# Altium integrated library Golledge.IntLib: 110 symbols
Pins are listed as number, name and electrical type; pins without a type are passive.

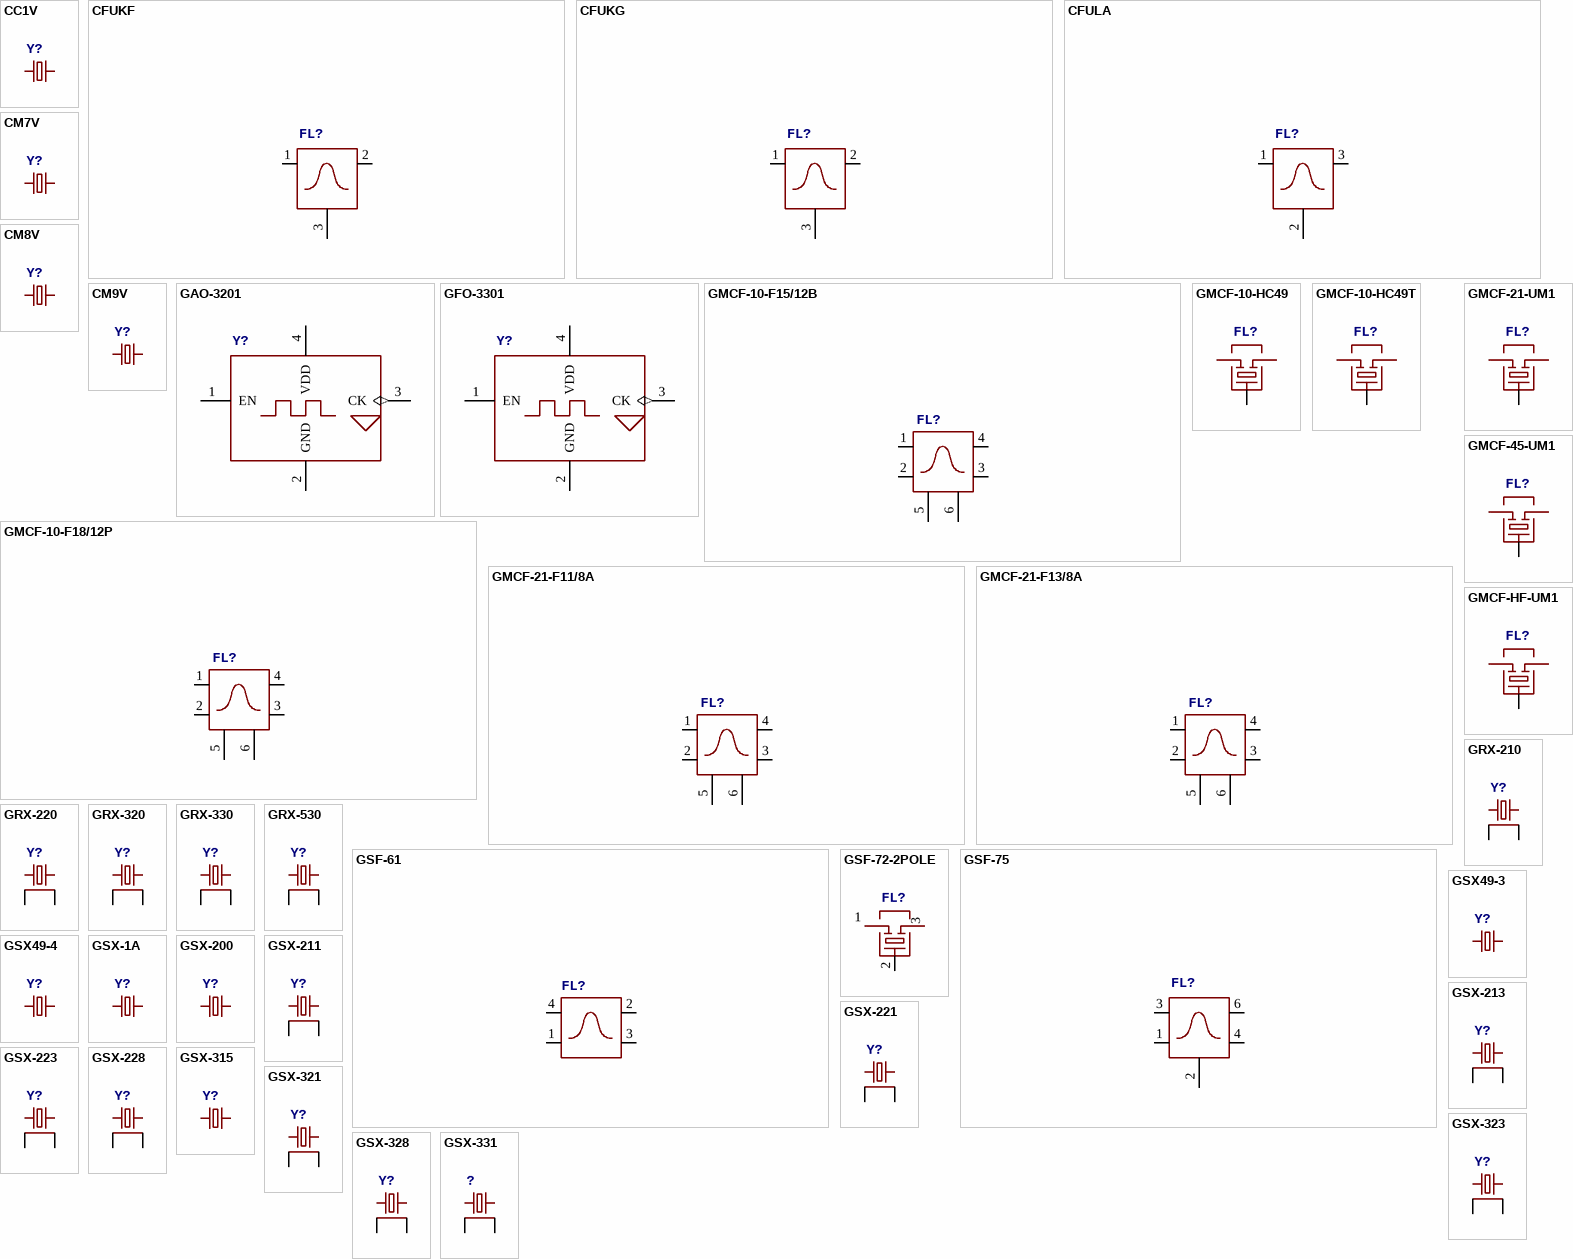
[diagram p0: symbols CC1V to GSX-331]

## CC1V
designator Y?  (value not drawn)
Crystal ¦SM¦ 8.0 x 3.7 mm ¦ Frequency Range 10kHz - 2.1 MHz; Latest Revision Note: Created
footprint CC1V
pins: '1' 1, '2' 2

## CFUKF
designator FL?  (value not drawn)
Ceramic Filter ¦SM¦ Murata¦ Frequency Range 455 kHz; Latest Revision Note: Created
footprint D0278-A
pins: 1 IN, 2 OUT, 3 GND

## CFUKG
designator FL?  (value not drawn)
Ceramic Filter ¦SM¦ Murata¦ Frequency Range 455 kHz; Latest Revision Note: Created
footprint D0278-A
pins: 1 IN, 2 OUT, 3 GND

## CFULA
designator FL?  (value not drawn)
Ceramic Filter ¦Leaded¦ Murata¦ Frequency Range 455 kHz; Latest Revision Note: Created
footprint D0274-A
pins: 1 IN, 2 GND, 3 OUT

## CM7V
designator Y?  (value not drawn)
Crystal ¦SM¦ 3.2 x 1.5 mm ¦ Tuning Fork (Watch)¦ Frequency Range 32.768kHz; Latest Revision Note: Created
footprint CM7V
pins: 1, 2

## CM8V
designator Y?  (value not drawn)
Crystal ¦SM¦ 2 x 1.2 mm ¦ Tuning Fork (Watch)¦ Frequency Range 32.768kHz; Latest Revision Note: Created
footprint CM8V
pins: 1, 2

## CM9V
designator Y?  (value not drawn)
Crystal ¦SM¦ 1.6 x 1.0 mm ¦ Tuning Fork (Watch)¦ Frequency Range 32.768kHz; Latest Revision Note: Created
footprint D0351-A
pins: 1, 2

## GAO-3201
designator Y?  (value not drawn)
Oscillator ¦SM¦ 2.5 x 2.0 mm ¦ CMOS output ¦ Frequency Range 32.768kHz; Latest Revision Note: Created
footprint OSC2520
pins: 1 EN, 2 GND (power), 3 CK (out), 4 VDD (power)

## GFO-3301
designator Y?  (value not drawn)
Oscillator ¦SM¦ 3.2 x 2.5 mm ¦ CMOS output ¦ Frequency Range 32.768kHz; Latest Revision Note: Created
footprint OSC3225
pins: 1 EN, 2 GND (power), 3 CK (out), 4 VDD (power)

## GMCF-10-F15/12B
designator FL?  (value not drawn)
Crystal Filters ¦Leaded¦ 6 pole ¦ Frequency Range 10.7 MHz; Latest Revision Note: Created
footprint F15/12B
pins: 1 IN, 2 GND@1, 3 GND@2, 4 OUT, 5 CASE@1, 6 CASE@2

## GMCF-10-F18/12P
designator FL?  (value not drawn)
Crystal Filters ¦Leaded¦ 8 pole ¦ Frequency Range 10.7 MHz; Latest Revision Note: Created
footprint F18/12P
pins: 1 IN, 2 GND@1, 3 GND@2, 4 OUT, 5 CASE@1, 6 CASE@2

## GMCF-10-HC49
designator FL?  (value not drawn)
Crystal Filter ¦Leaded¦ Monolithic¦ Frequency Range 10.7 MHz; Latest Revision Note: Created
footprint HC49U
pins: 1, 2, 3

## GMCF-10-HC49T
designator FL?  (value not drawn)
Crystal Filter ¦Leaded¦ Monolithic¦ Frequency Range 10.7 MHz; Latest Revision Note: Created
footprint HC49U
pins: 1, 2, 3

## GMCF-21-F11/8A
designator FL?  (value not drawn)
Crystal Filters ¦Leaded¦ 6 and 8 pole ¦ Frequency Range 21.4 MHz; Latest Revision Note: Created
footprint F11/8A
pins: 1 IN, 2 GND@1, 3 GND@2, 4 OUT, 5 CASE@1, 6 CASE@2

## GMCF-21-F13/8A
designator FL?, comment GMCF-21-EF13/8A  (value not drawn)
Crystal Filters ¦Leaded¦ 10 pole ¦ Frequency Range 10.7 - 21.4 MHz; Latest Revision Note: Created
footprint F13/8A
pins: 1 IN, 2 GND@1, 3 GND@2, 4 OUT, 5 CASE_1, 6 CASE_2

## GMCF-21-UM1
designator FL?  (value not drawn)
Crystal Filter ¦Leaded¦ Monolithic¦ Frequency Range 21.4 MHz; Latest Revision Note: Created
footprint UM1
footprint UM4
footprint UM5
pins: 1, 2, 3

## GMCF-45-UM1
designator FL?  (value not drawn)
Crystal Filter ¦Leaded¦ Monolithic¦ Frequency Range 45 MHz; Latest Revision Note: Created
footprint UM1
footprint UM4
footprint UM5
pins: 1, 2, 3

## GMCF-HF-UM1
designator FL?  (value not drawn)
Crystal Filter ¦Leaded¦ Monolithic¦ Frequency Range 55 - 90 MHz; Latest Revision Note: Created
footprint UM1
footprint UM4
footprint UM5
pins: 1, 2, 3

## GRX-210
designator Y?  (value not drawn)
Crystal ¦SM¦ 1.6 x 1.2 mm ¦ AT cut ¦ Frequency Range 26 - 40 MHz; Latest Revision Note: Created
footprint GSX-211
pins: 1, 2, 3, 4

## GRX-220
designator Y?
Crystal ¦SM¦ 2.0 x 1.6 mm ¦ AT cut ¦ Frequency Range 16 - 26 MHz; Latest Revision Note: Created
footprint GSX-221
pins: 1, 2, 3, 4

## GRX-320
designator Y?  (value not drawn)
Crystal ¦SM¦ 2.5 x 2.0 mm ¦ AT cut ¦ Frequency Range 12 - 40 MHz; Latest Revision Note: Created
footprint OSC2520
pins: 1, 2, 3, 4

## GRX-330
designator Y?  (value not drawn)
Crystal ¦SM¦ 3.2 x 2.5 mm ¦ AT cut ¦ Frequency Range 12 - 40 MHz; Latest Revision Note: Created
footprint OSC3225
pins: 1, 2, 3, 4

## GRX-530
designator Y?  (value not drawn)
Crystal ¦SM¦ 5.0 x 3.2 mm ¦ AT cut ¦ Frequency Range 9.8 - 40 MHz; Latest Revision Note: Created
footprint GSX-531
pins: 1, 2, 3, 4

## GSF-61
designator FL?  (value not drawn)
Crystal Filter ¦SM¦ 6.0 x 3.5 ¦ Frequency Range 20 - 45 MHz; Latest Revision Note: Created
footprint D0216-A
pins: 1 INBAR_OR_GND@1, 2 OUT, 3 OUTBAR_OR_GND@2, 4 IN

## GSF-72-2POLE
designator FL?  (value not drawn)
Crystal Filter ¦SM¦ Monolithic¦ Frequency Range 21.4 - 45 MHz; Latest Revision Note: Created
footprint GSF-72
pins: 1, 2, 3

## GSF-75
designator FL?  (value not drawn)
Crystal Filter ¦SM¦ 7.0 x 5.0 ¦ Frequency Range 21.4 - 75 MHz; Latest Revision Note: Created
footprint GSF-75
pins: 1 INBAR_OR_GND@1, 2 COUPLING_CAP, 3 IN, 4 OUTBAR_OR_GND@2, 6 OUT

## GSX49-3
designator Y?  (value not drawn)
Crystal ¦SM¦ 12.3 x 4.7 mm ¦ Low cost ¦ Frequency Range 3.18 - 90 MHz; Latest Revision Note: Created
footprint GSX49-3
pins: 1, 2

## GSX49-4
designator Y?  (value not drawn)
Crystal ¦SM¦ 12.3 x 4.7 mm ¦ Low cost ¦ Frequency Range 3.18 - 90 MHz; Latest Revision Note: Created
footprint GSX49-4
pins: 1, 2

## GSX-1A
designator Y?  (value not drawn)
Crystal ¦SM¦ 7.5 x 5.0 mm ¦ Low cost ¦ Frequency Range 5.0 - 84 MHz; Latest Revision Note: Created
footprint D0118-C
pins: 1, 2

## GSX-200
designator Y?  (value not drawn)
Crystal ¦SM¦ 7.9 x 3.7 mm ¦ Plastic moulded Tuning Fork (Watch) ¦ Frequency Range 32.768kHz; Latest Revision Note: Created
footprint GSX-200
pins: 1, 4 2

## GSX-211
designator Y?  (value not drawn)
Crystal ¦SM¦ 1.6 x 1.2 mm ¦ AT cut ¦ Frequency Range 24 - 54 MHz; Latest Revision Note: Created
footprint GSX-211
pins: 1, 2, 3, 4

## GSX-213
designator Y?  (value not drawn)
Crystal ¦SM¦ 1.6 x 1.2 mm ¦ AT cut ¦ Frequency Range 26 - 60 MHz; Latest Revision Note: Created
footprint GSX-211
pins: 1, 2, 3, 4

## GSX-221
designator Y?  (value not drawn)
Crystal ¦SM¦ 2.0 x 1.6 mm ¦ AT cut ¦ Frequency Range 16 - 56 MHz; Latest Revision Note: Created
footprint GSX-221
pins: 1, 2, 3, 4

## GSX-223
designator Y?  (value not drawn)
Crystal ¦SM¦ 2.0 x 1.6 mm ¦ AT cut ¦ Frequency Range 16 - 50 MHz; Latest Revision Note: Created
footprint GSX-221
pins: 1, 2, 3, 4

## GSX-228
designator Y?  (value not drawn)
Crystal ¦SM¦ 2.0 x 1.6 mm ¦ AT cut ¦ Frequency Range 20 - 315 MHz; Latest Revision Note: Created
footprint GSX-221
pins: 1, 2, 3, 4

## GSX-315
designator Y?  (value not drawn)
Crystal ¦SM¦ 3.2 x 1.5 mm ¦ Tuning Fork (Watch)¦ Frequency Range 32.768 kHz; Latest Revision Note: Created
footprint GSX-315
pins: 1, 2

## GSX-321
designator Y?  (value not drawn)
Crystal ¦SM¦ 2.5 x 2.0 mm ¦ AT cut ¦ Frequency Range 12 - 66 MHz; Latest Revision Note: Created
footprint OSC2520
pins: 1, 2, 3, 4

## GSX-323
designator Y?  (value not drawn)
Crystal ¦SM¦ 2.5 x 2.0 mm ¦ AT cut ¦ Frequency Range 12 - 54 MHz; Latest Revision Note: Created
footprint OSC2520
pins: 1, 2, 3, 4

## GSX-328
designator Y?  (value not drawn)
Crystal ¦SM¦ 2.5 x 2.0 mm ¦ AT cut ¦ Frequency Range 16 - 315 MHz; Latest Revision Note: Created
footprint OSC2520
pins: 1, 2, 3, 4

## GSX-331
designator ?  (value not drawn)
Crystal ¦SM¦ 3.2 x 2.5 mm ¦ AT cut ¦ Frequency Range 10 - 125 MHz; Latest Revision Note: Created
footprint OSC3225
pins: 1, 2, 3, 4

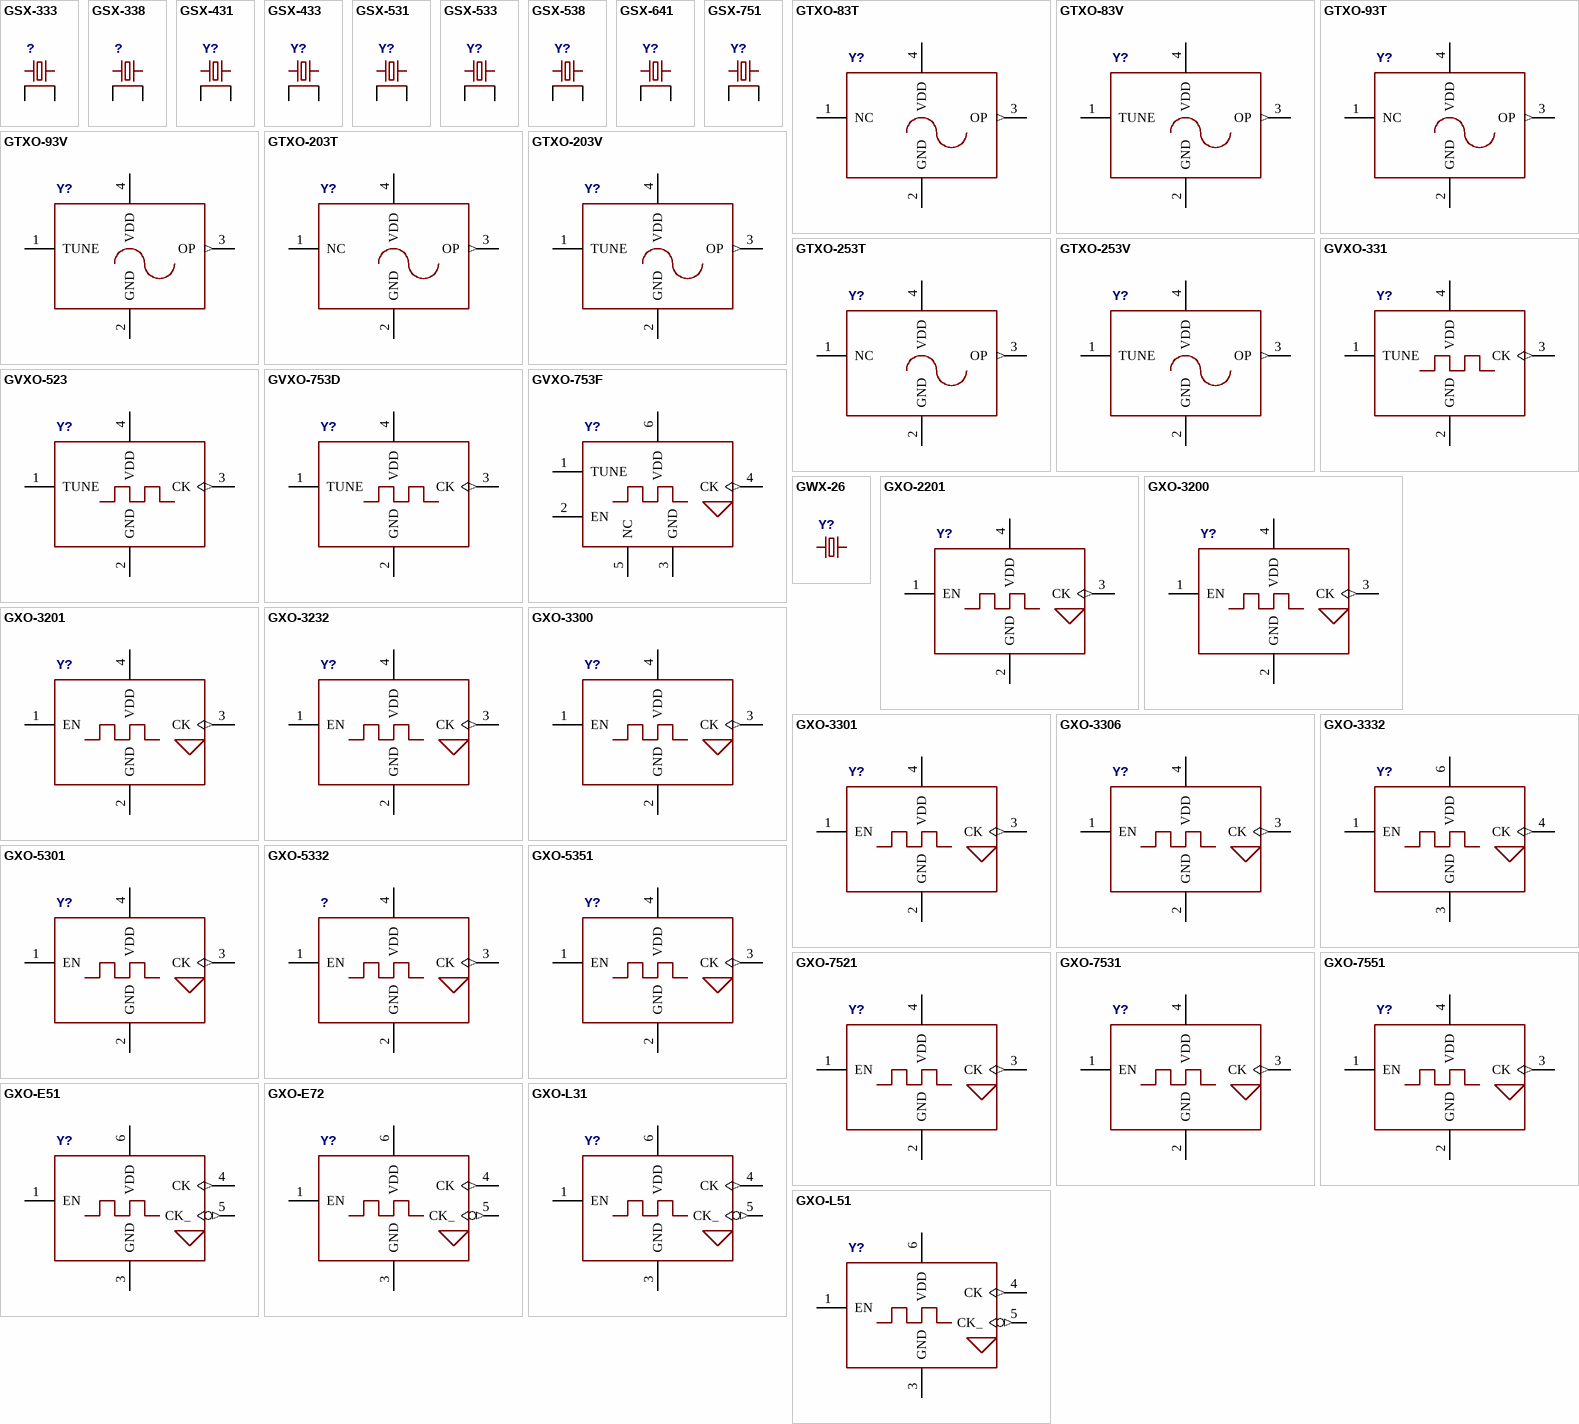
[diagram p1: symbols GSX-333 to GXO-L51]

## GSX-333
designator ?  (value not drawn)
Crystal ¦SM¦ 3.2 x 2.5 mm ¦ AT cut ¦ Frequency Range 12 - 125 MHz; Latest Revision Note: Created
footprint OSC3225
pins: 1, 2, 3, 4

## GSX-338
designator ?  (value not drawn)
Crystal ¦SM¦ 3.2 x 2.5 mm ¦ AT cut ¦ Frequency Range 10 - 315 MHz; Latest Revision Note: Created
footprint D0262-C
pins: 1, 2, 3, 4

## GSX-431
designator Y?  (value not drawn)
Crystal ¦SM¦ 4.0 x 2.5 mm ¦ AT cut ¦ Frequency Range 13 - 32 MHz; Latest Revision Note: Created
footprint GSX-431
pins: 1, 2, 3, 4

## GSX-433
designator Y?  (value not drawn)
Crystal ¦SM¦ 4.0 x 2.5 mm ¦ AT cut ¦ Frequency Range 12 - 44 MHz; Latest Revision Note: Created
footprint GSX-431
pins: 1, 2, 3, 4

## GSX-531
designator Y?  (value not drawn)
Crystal ¦SM¦ 5.0 x 3.2 mm ¦ AT cut ¦ Frequency Range 8 - 100 MHz; Latest Revision Note: Created
footprint GSX-531
pins: 1, 2, 3, 4

## GSX-533
designator Y?  (value not drawn)
Crystal ¦SM¦ 5.0 x 3.2 mm ¦ AT cut ¦ Frequency Range 8 - 160 MHz; Latest Revision Note: Created
footprint GSX-531
pins: 1, 2, 3, 4

## GSX-538
designator Y?  (value not drawn)
Crystal ¦SM¦ 5.0 x 3.2 mm ¦ AT cut ¦ Frequency Range 8 - 315 MHz; Latest Revision Note: Created
footprint GSX-531
pins: 1, 2, 3, 4

## GSX-641
designator Y?  (value not drawn)
Crystal ¦SM¦ 6.0 x 3.5 mm ¦ AT cut ¦ Frequency Range 9.2 - 45.0 MHz; Latest Revision Note: Created
footprint D0162-A
pins: 1, 2, 3, 4

## GSX-751
designator Y?  (value not drawn)
Crystal ¦SM¦ 7.0 x 5.0 mm ¦ AT cut ¦ Frequency Range 6 - 100 MHz; Latest Revision Note: Created
footprint GSX-751
pins: 1, 2, 3, 4

## GTXO-83T
designator Y?  (value not drawn)
TCXO ¦SM¦ 5.0 x 3.2 mm ¦ 2.4V - 5.5V ¦ Frequency Range 6 - 45 MHz; Latest Revision Note: Created
footprint TCOSC5032
pins: 1 NC, 2 GND (power), 3 OP (out), 4 VDD (power)

## GTXO-83V
designator Y?  (value not drawn)
VCTCXO ¦SM¦ 5.0 x 3.2 mm ¦ 2.4V - 5.5V ¦ Frequency Range 6 - 45 MHz; Latest Revision Note: Created
footprint TCOSC5032
pins: 1 TUNE, 2 GND (power), 3 OP (out), 4 VDD (power)

## GTXO-93T
designator Y?  (value not drawn)
TCXO ¦SM¦ 3.2 x 2.5 mm ¦ 1.8V - 3.6V ¦ Frequency Range 10 - 52 MHz; Latest Revision Note: Created
footprint D0303-A
pins: 1 NC, 2 GND (power), 3 OP (out), 4 VDD (power)

## GTXO-93V
designator Y?  (value not drawn)
VCTCXO ¦SM¦ 3.2 x 2.5 mm ¦ 1.8V - 3.6V ¦ Frequency Range 10 - 52 MHz; Latest Revision Note: Created
footprint D0303-A
pins: 1 TUNE, 2 GND (power), 3 OP (out), 4 VDD (power)

## GTXO-203T
designator Y?  (value not drawn)
TCXO ¦SM¦ 2.0 x 1.6 mm ¦ 1.8V - 3.6V ¦ Frequency Range 26 - 52 MHz; Latest Revision Note: Created
footprint OSC2016
pins: 1 NC, 2 GND (power), 3 OP (out), 4 VDD (power)

## GTXO-203V
designator Y?  (value not drawn)
TCXO ¦SM¦ 2.0 x 1.6 mm ¦ 1.8V - 3.6V ¦ Frequency Range 26 - 52 MHz; Latest Revision Note: Created
footprint OSC2016
pins: 1 TUNE, 2 GND (power), 3 OP (out), 4 VDD (power)

## GTXO-253T
designator Y?  (value not drawn)
TCXO ¦SM¦ 2.5 x 2.0 mm ¦ 1.8V - 3.6V ¦ Frequency Range 10 - 52 MHz; Latest Revision Note: Created
footprint OSC2520
pins: 1 NC, 2 GND (power), 3 OP (out), 4 VDD (power)

## GTXO-253V
designator Y?  (value not drawn)
VCTCXO ¦SM¦ 2.5 x 2.0 mm ¦ 1.8V - 3.6V ¦ frequency Range 10 - 52 MHz; Latest Revision Note: Created
footprint OSC2520
pins: 1 TUNE, 2 GND (power), 3 OP (out), 4 VDD (power)

## GVXO-331
designator Y?  (value not drawn)
VCXO ¦SM¦ 3.2 x 2.5 mm ¦ 1.8V - 3.3V CMOS output ¦ Frequency Range 1.5 - 64.44 MHz; Latest Revision Note: Created
footprint OSC3225
pins: 1 TUNE, 2 GND (power), 3 CK (out), 4 VDD (power)

## GVXO-523
designator Y?  (value not drawn)
VCXO ¦SM¦ 5.0 x 3.2 mm ¦ 3.3V CMOS output ¦ Frequency Range 1.5 - 61.44 MHz; Latest Revision Note: Created
footprint OSC5032
pins: 1 TUNE, 2 GND (power), 3 CK (out), 4 VDD (power)

## GVXO-753D
designator Y?  (value not drawn)
VCXO ¦SM¦ 7.0 x 5.0 mm ¦ 3.3V CMOS output ¦ Frequency Range 1.5 - 54 MHz; Latest Revision Note: Created
footprint OSC7050
pins: 1 TUNE, 2 GND (power), 3 CK (out), 4 VDD (power)

## GVXO-753F
designator Y?  (value not drawn)
VCXO ¦SM¦ 7.0 x 5.0 mm ¦ 3.3V CMOS output ¦ Frequency Range 1.5 - 54 MHz; Latest Revision Note: Created
footprint OSC7050PADS6
pins: 1 TUNE, 2 EN, 3 GND (power), 4 CK (out), 5 NC, 6 VDD (power)

## GWX-26
designator Y?  (value not drawn)
Crystal ¦Leaded¦ Cylindrical 2.0 x6.0 mm ¦ Tuning Fork (Watch)¦ Frequency Range 32.768 kHz; Latest Revision Note: Created
footprint GWX-26
pins: 1, 2

## GXO-2201
designator Y?  (value not drawn)
Oscillator ¦SM¦ 2.05 x 1.65 mm ¦ 1.8V - 3.3V ¦ Frequency Range 1.5 - 54 MHz; Latest Revision Note: Created
footprint GSX-221
pins: 1 EN, 2 GND (power), 3 CK (out), 4 VDD (power)

## GXO-3200
designator Y?  (value not drawn)
Oscillator ¦SM¦ 2.5 x 2.0 mm ¦ 1.8V - 3.3V ¦ Frequency Range 1.8 - 170 MHz; Latest Revision Note: Created
footprint OSC2520
pins: 1 EN, 2 GND (power), 3 CK (out), 4 VDD (power)

## GXO-3201
designator Y?  (value not drawn)
Oscillator ¦SM¦ 2.5 x 2.0 mm ¦ 1.8V - 3.3V ¦ Frequency Range 0.75 - 50 MHz; Latest Revision Note: Created
footprint OSC2520
pins: 1 EN, 2 GND (power), 3 CK (out), 4 VDD (power)

## GXO-3232
designator Y?  (value not drawn)
Oscillator ¦SM¦ 2.5 x 2.0 mm ¦ Tight Stability ¦ Frequency Range 4 - 54 MHz; Latest Revision Note: Created
footprint OSC2520
pins: 1 EN, 2 GND (power), 3 CK (out), 4 VDD (power)

## GXO-3300
designator Y?  (value not drawn)
Oscillator ¦SM¦ 3.2 x 2.5 mm ¦ 3.3V ¦ Frequency 10 - 160 MHz; Latest Revision Note: Created
footprint OSC3225
pins: 1 EN, 2 GND (power), 3 CK (out), 4 VDD (power)

## GXO-3301
designator Y?  (value not drawn)
Oscillator ¦SM¦ 3.2 x 2.5 mm ¦ 1.8V - 3.3V ¦ Frequency Range 0.625 - 75 MHz; Latest Revision Note: Created
footprint OSC3225
pins: 1 EN, 2 GND (power), 3 CK (out), 4 VDD (power)

## GXO-3306
designator Y?  (value not drawn)
Oscillator ¦SM¦ 3.2 x 2.5 mm ¦ 1.8V - 3.3V ¦ Frequency 22.5792, 24.576, 45.1584, 49.152 MHz; Latest Revision Note: Created
footprint OSC3225
pins: 1 EN, 2 GND (power), 3 CK (out), 4 VDD (power)

## GXO-3332
designator Y?  (value not drawn)
Oscillator ¦SM¦ 3.2 x 2.5 mm ¦ Tight Stability ¦ Frequency Range 2.5 - 60 MHz; Latest Revision Note: Created
footprint OSC3225PADS6
pins: 1 EN, 3 GND (power), 4 CK (out), 6 VDD (power)

## GXO-5301
designator Y?  (value not drawn)
Oscillator ¦SM¦ 5.0 x 3.2 mm ¦ 1.8 ~ 3.3 V ¦ Frequency Range 0.5 - 156.25 MHz; Latest Revision Note: Created
footprint OSC5032
pins: 1 EN, 2 GND (power), 3 CK (out), 4 VDD (power)

## GXO-5332
designator ?  (value not drawn)
Oscillator ¦SM¦ 5.0 x 3.2 mm ¦ 2.5 ~ 3.3 V Tight Stability ¦ Frequency Range 4 - 54 MHz; Latest Revision Note: Created
footprint TCOSC5032
pins: 1 EN, 2 GND (power), 3 CK (out), 4 VDD (power)

## GXO-5351
designator Y?  (value not drawn)
Oscillator ¦SM¦ 5.0 x 3.2 mm ¦ 5V ¦ Frequency Range 0.5 - 110 MHz; Latest Revision Note: Created
footprint OSC5032
pins: 1 EN, 2 GND (power), 3 CK (out), 4 VDD (power)

## GXO-7521
designator Y?  (value not drawn)
Oscillator ¦SM¦ 7.0 x 5.0 mm ¦ 1.8 ~ 2.8 V ¦ Frequency Range 0.5 - 160 MHz; Latest Revision Note: Created
footprint OSC7050
pins: 1 EN, 2 GND (power), 3 CK (out), 4 VDD (power)

## GXO-7531
designator Y?  (value not drawn)
Oscillator ¦SM¦ 7.0 x 5.0 mm ¦ 3.3 V ¦ Frequency Range 0.5 - 200 MHz; Latest Revision Note: Created
footprint OSC7050
pins: 1 EN, 2 GND (power), 3 CK (out), 4 VDD (power)

## GXO-7551
designator Y?  (value not drawn)
Oscillator ¦SM¦ 7.0 x 5.0 mm ¦ 5V ¦ Frequency Range 0.5 - 107 MHz; Latest Revision Note: Created
footprint OSC7050
pins: 1 EN, 2 GND (power), 3 CK (out), 4 VDD (power)

## GXO-E51
designator Y?  (value not drawn)
Oscillator ¦SM¦ 5.2 x 3.2 mm ¦ LV-PECL ¦ Frequency Range 50 - 250 MHz; Latest Revision Note: Created
footprint D0342-C
pins: 1 EN, 3 GND (power), 4 CK (out), 5 CK_ (out), 6 VDD (power)

## GXO-E72
designator Y?  (value not drawn)
Oscillator ¦SM¦ 7.0 x 5.0 mm ¦ LV-PECL ¦ Frequency Range 40 - 200 MHz; Latest Revision Note: Created
footprint OSC7050PADS6
pins: 1 EN, 3 GND (power), 4 CK (out), 5 CK_ (out), 6 VDD (power)

## GXO-L31
designator Y?  (value not drawn)
Oscillator ¦SM¦ 3.2 x 2.5 mm ¦ LVDS ¦ Frequency Range 40 - 250 MHz; Latest Revision Note: Created
footprint OSC3225P6F
pins: 1 EN, 3 GND (power), 4 CK (out), 5 CK_ (out), 6 VDD (power)

## GXO-L51
designator Y?  (value not drawn)
Oscillator ¦SM¦ 5.2 x 3.2 mm ¦ LVDS ¦ Frequency Range 50 - 250 MHz; Latest Revision Note: Created
footprint D0342-C
pins: 1 EN, 3 GND (power), 4 CK (out), 5 CK_ (out), 6 VDD (power)

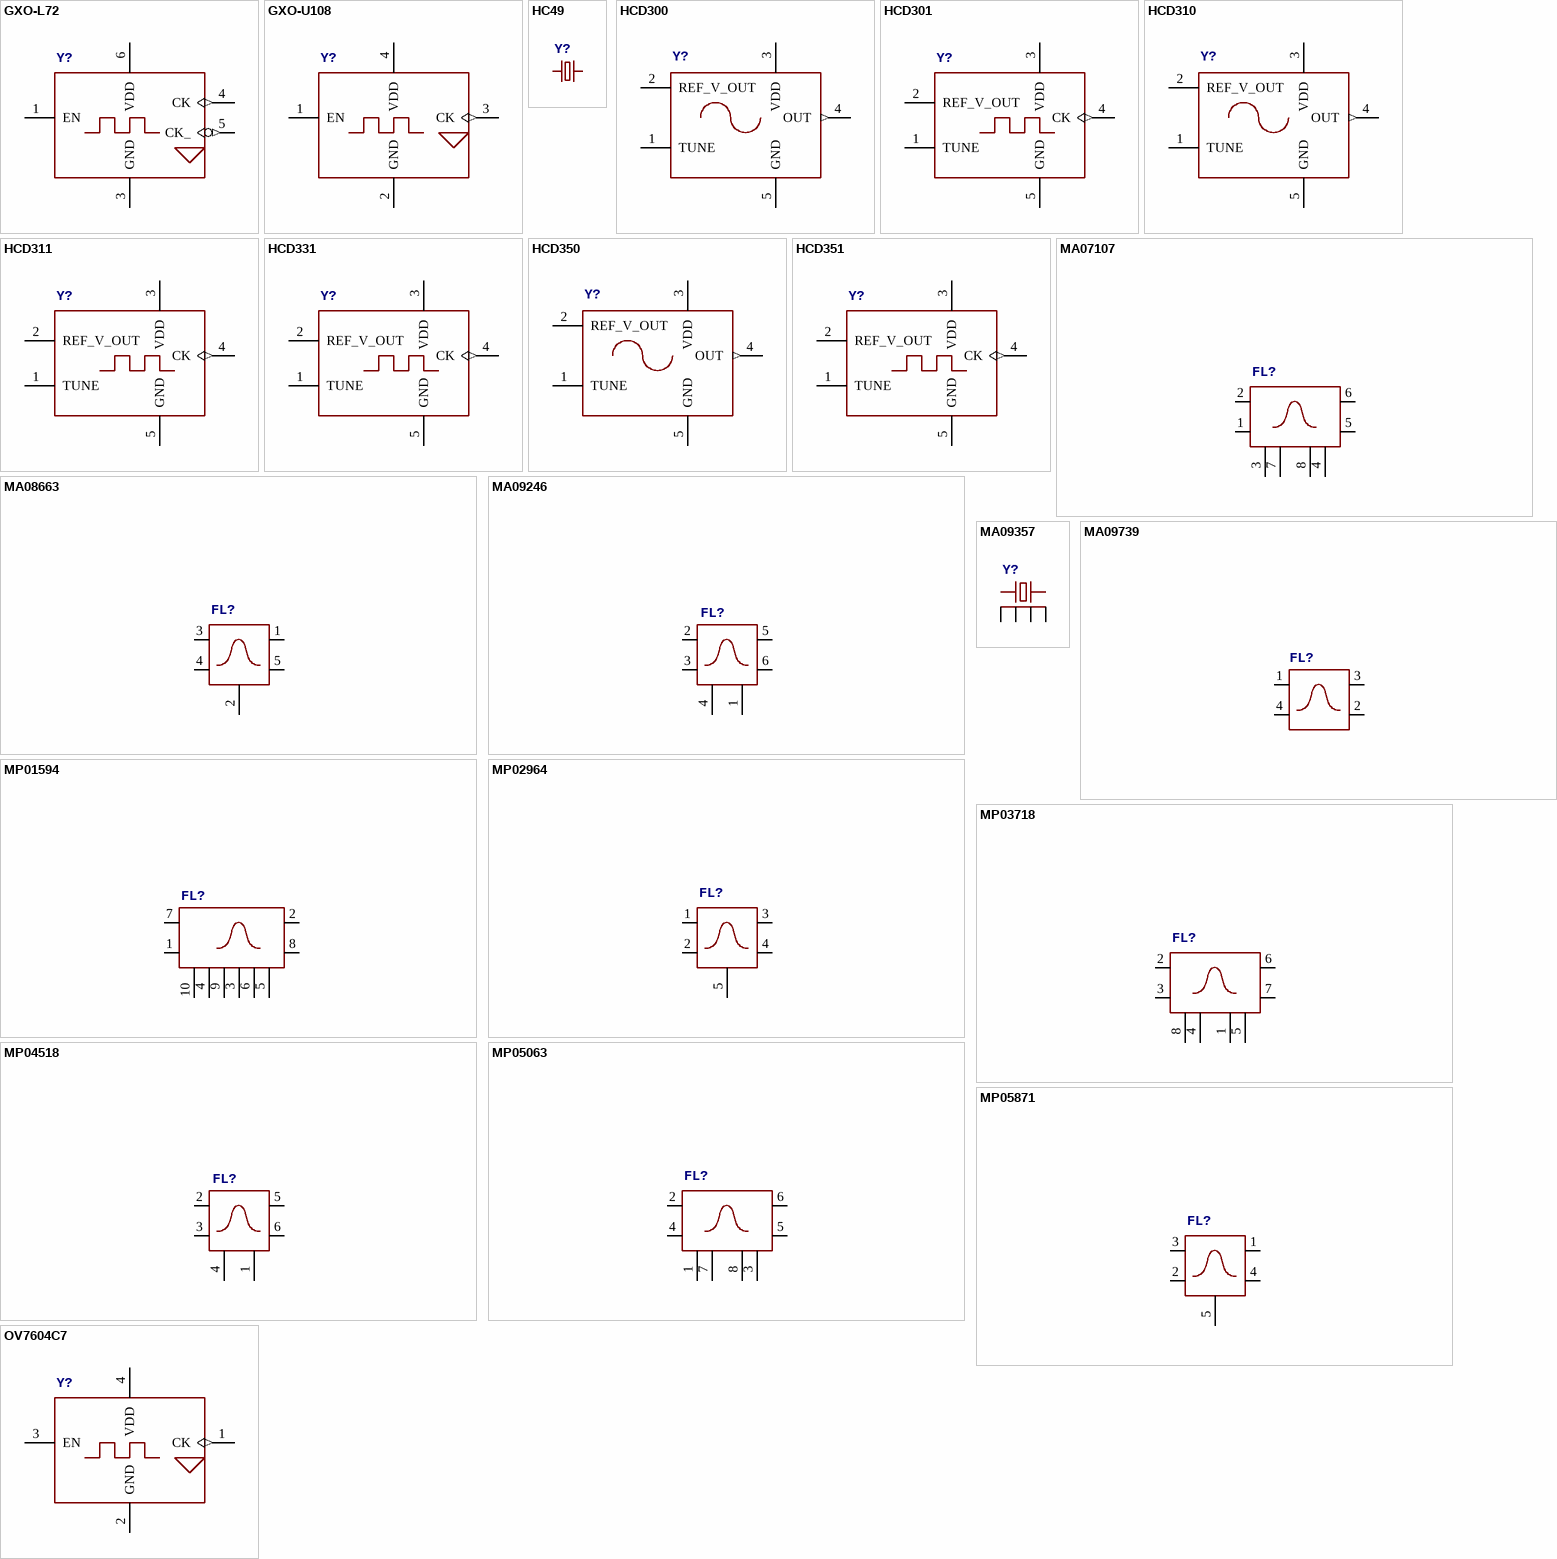
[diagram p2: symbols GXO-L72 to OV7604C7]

## GXO-L72
designator Y?  (value not drawn)
Oscillator ¦SM¦ 7.0 x 5.0 mm ¦ LVDS ¦ Frequency Range 80 - 200 MHz; Latest Revision Note: Created
footprint OSC7050PADS6
pins: 1 EN, 3 GND (power), 4 CK (out), 5 CK_ (out), 6 VDD (power)

## GXO-U108
designator Y?  (value not drawn)
Oscillator ¦SM¦ 7.5 x 5.0 mm ¦ 3.5, 5.0 V ¦ Frequency Range 12kHz - 170MHz; Latest Revision Note: Created
footprint D0135-B
pins: 1 EN, 2 GND (power), 3 CK (out), 4 VDD (power)

## HC49
designator Y?  (value not drawn)
Crystal ¦Leaded¦ 11.1 x 4.7 x 13.5 mm ¦ AT cut ¦ Frequency Range 1 - 160 MHz; Latest Revision Note: Created
footprint D0119-A
pins: 1, 2

## HCD300
designator Y?  (value not drawn)
OCXO ¦ low profile ¦ 5V Sine output ¦ Frequency Range 5 - 20 MHz; Latest Revision Note: Created
footprint EURO_5PIN_OCXO
pins: 1 TUNE, 2 REF_V_OUT, 3 VDD (power), 4 OUT (out), 5 GND (power)

## HCD301
designator Y?  (value not drawn)
OCXO ¦ Low profile ¦ 5V CMOS output ¦ Frequency Range 5 - 20 MHz; Latest Revision Note: Created
footprint EURO_5PIN_OCXO
pins: 1 TUNE, 2 REF_V_OUT, 3 VDD (power), 4 CK (out), 5 GND (power)

## HCD310
designator Y?  (value not drawn)
OCXO ¦ Low profile ¦ 12V Sine output ¦ Frequency Range 5 - 60 MHz; Latest Revision Note: Created
footprint EURO_5PIN_OCXO
pins: 1 TUNE, 2 REF_V_OUT, 3 VDD (power), 4 OUT (out), 5 GND (power)

## HCD311
designator Y?  (value not drawn)
OCXO ¦ Low profile ¦ 12V CMOS output ¦ Frequency Range 5 - 60 MHz; Latest Revision Note: Created
footprint EURO_5PIN_OCXO
pins: 1 TUNE, 2 REF_V_OUT, 3 VDD (power), 4 CK (out), 5 GND (power)

## HCD331
designator Y?  (value not drawn)
OCXO ¦ Low Profile ¦ 5V CMOS output ¦ Frequency Range 13 - 20 MHz; Latest Revision Note: Created
footprint EURO_5PIN_OCXO
pins: 1 TUNE, 2 REF_V_OUT, 3 VDD (power), 4 CK (out), 5 GND (power)

## HCD350
designator Y?  (value not drawn)
OCXO ¦ Standard package ¦ 5V Sine output ¦ Frequency Range 5 - 20 MHz; Latest Revision Note: Created
footprint EURO_5PIN_OCXO
pins: 1 TUNE, 2 REF_V_OUT, 3 VDD (power), 4 OUT (out), 5 GND (power)

## HCD351
designator Y?  (value not drawn)
OCXO ¦ Standard Package ¦ 5V CMOS output ¦ Frequency Range 5 - 20 MHz; Latest Revision Note: Created
footprint EURO_5PIN_OCXO
pins: 1 TUNE, 2 REF_V_OUT, 3 VDD (power), 4 CK (out), 5 GND (power)

## MA07107
designator FL?, comment SAW Filter 169MHz  (value not drawn)
Latest Revision Note: Created
footprint SAW5X5
pins: 1 INBAR_OR_GND@1, 2 IN, 3 CASE@1, 4 CASE@2, 5 OUTBAR_OR_GND@2, 6 OUT, 7 P$1, 8 P$2

## MA08663
designator FL?  (value not drawn)
SAW Filter 907.50MHz    Single ended in to Balanced out operation Terminating source impedance: ZS = 50 ohm Terminating load impedance: ZL = 150 ohm // 60nH; Latest Revision Note: Created
footprint SAW2.5X2.0P5
pins: 1 OUT, 2 CASE@1, 3 IN, 4 INBAR_OR_GND@1, 5 OUTBAR_OR_GND@2

## MA09246
designator FL?, comment SAW Filter 433.920MHz  (value not drawn)
Latest Revision Note: Created
footprint SAW3.8X3.8P6
pins: 1 CASE@2, 2 IN, 3 GND@1, 4 CASE@1, 5 OUT, 6 GND@2

## MA09357
designator Y?  (value not drawn)
SAW resonator ¦SM¦ 3.0 x 3.0 mm ¦ Frequency 500MHz Model TC0378A Datasheet; Latest Revision Note: Created
footprint SAW3X3P6
pins: 1, 2, 3, 4, 5, 6

## MA09739
designator FL?, comment SAW Filter 1642.50MHz  (value not drawn)
Latest Revision Note: Created
footprint SAW2.5X2.0P4
pins: 1 IN, 2 OUTBAR_OR_GND@2, 3 OUT, 4 INBAR_OR_GND@1

## MP01594
designator FL?, comment SAW Filter 159.01250MHz  (value not drawn)
Latest Revision Note: Created
footprint SAW7X5
pins: 1 INBAR_OR_GND@1, 2 OUT, 3 P$3, 4 CASE@1, 5 CASE@2, 6 P$2, 7 IN, 8 OUTBAR_OR_GND@2, 9 P$1, 10 CASE@3

## MP02964
designator FL?  (value not drawn)
SAW filter 70MHz CF, 1MHz 1dB BW.; Latest Revision Note: Created
footprint SAW13X7
pins: 1 IN, 2 INBAR_OR_GND@1, 3 OUT, 4 OUTBAR_OR_GND@2, 5 CASE@1

## MP03718
designator FL?  (value not drawn)
SAW Filter 402.0MHz; Latest Revision Note: Created
footprint SAW3.8X3.8P8
pins: 1 P$2, 2 IN, 3 INBAR_OR_GND@1, 4 P$1, 5 CASE@2, 6 OUT, 7 OUTBAR_OR_GND@2, 8 CASE@1

## MP04518
designator FL?, comment SAW Filter 418.0MHz  (value not drawn)
Latest Revision Note: Created
footprint SAW3X3P6
pins: 1 CASE@2, 2 IN, 3 GND@1, 4 CASE@1, 5 OUT, 6 GND@2

## MP05063
designator FL?, comment SAW Filter 404.0MHz  (value not drawn)
Latest Revision Note: Created
footprint SAW3X3P8
pins: 1 CASE@1, 2 IN, 3 CASE@2, 4 INBAR_OR_GND@1, 5 OUTBAR_OR_GND@2, 6 OUT, 7 P$1, 8 P$2

## MP05871
designator FL?, comment SAW Filter 897.0MHz  (value not drawn)
Latest Revision Note: Created
footprint SAW1.4X1.1P5
pins: 1 OUT, 2 INBAR_OR_GND@1, 3 IN, 4 OUTBAR_OR_GND@2, 5 CASE@1

## OV7604C7
designator Y?  (value not drawn)
Oscillator ¦SM¦ 3.2 x 1.5 mm ¦ Low Power CMOS output ¦ Frequency Range 32.768kHz; Latest Revision Note: Created
footprint OSC3215
pins: 1 CK (out), 2 GND (power), 3 EN, 4 VDD (power)

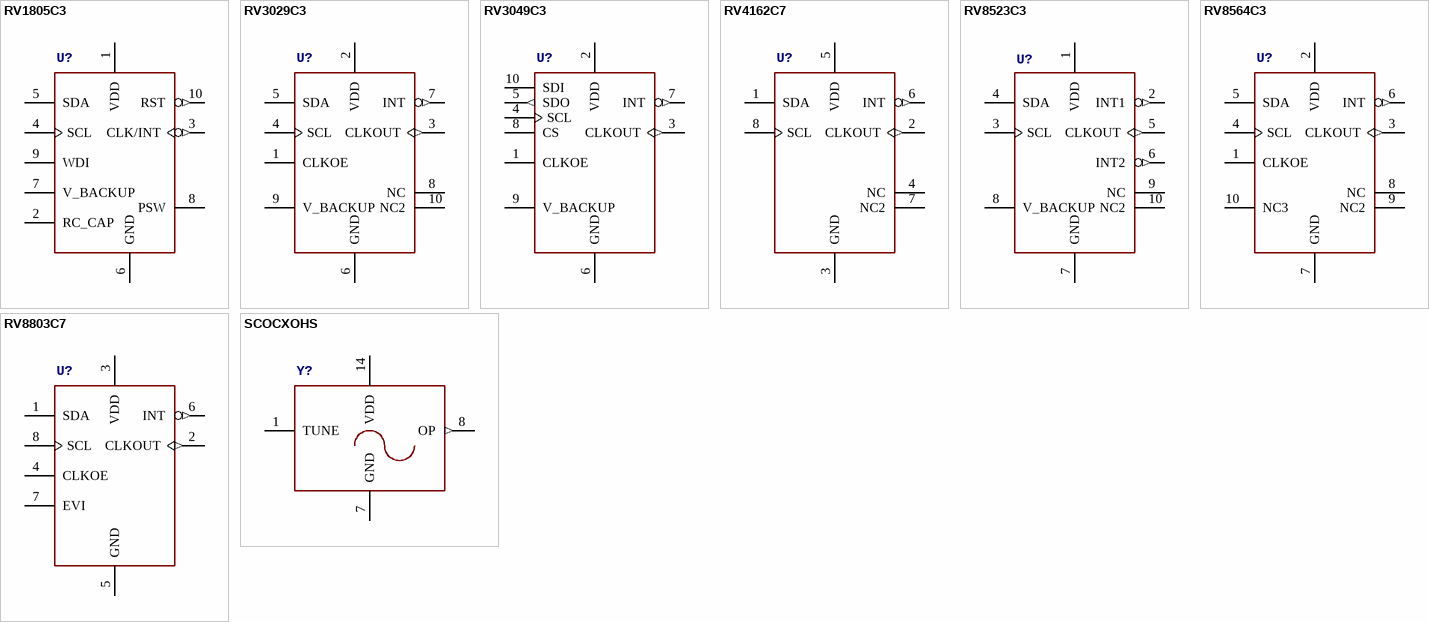
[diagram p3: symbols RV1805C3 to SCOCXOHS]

## RV1805C3
designator U?  (value not drawn)
Real Time Clock ¦SM¦ 3.7 x 2.5 mm ¦ I2C Bus ¦ Ultra Low Power; Latest Revision Note: Created
footprint RTC-C3
pins: 1 VDD (power), 2 RC_CAP, 3 CLK/INT (out), 4 SCL, 5 SDA, 6 GND (power), 7 V_BACKUP, 8 PSW, 9 WDI, 10 RST (out)

## RV3029C3
designator U?  (value not drawn)
Real Time Clock ¦SM¦ 3.7 x 2.5 mm ¦ I2C Bus ¦ Temperature compensated; Latest Revision Note: Created
footprint RTC-C3
pins: 1 CLKOE, 2 VDD (power), 3 CLKOUT (out), 4 SCL, 5 SDA, 6 GND (power), 7 INT (out), 8 NC, 9 V_BACKUP, 10 NC2

## RV3049C3
designator U?  (value not drawn)
Real Time Clock ¦SM¦ 3.7 x 2.5 mm ¦ SPI Bus ¦ Temperature compensated; Latest Revision Note: Created
footprint RTC-C3
pins: 1 CLKOE, 2 VDD (power), 3 CLKOUT (out), 4 SCL, 5 SDO (out), 6 GND (power), 7 INT (out), 8 CS, 9 V_BACKUP, 10 SDI

## RV4162C7
designator U?  (value not drawn)
Real Time Clock ¦SM¦ 3.2 x 1.5 mm ¦ I2C Bus; Latest Revision Note: Created
footprint RTC-C7
pins: 1 SDA, 2 CLKOUT (out), 3 GND (power), 4 NC, 5 VDD (power), 6 INT (out), 7 NC2, 8 SCL

## RV8523C3
designator U?
Real Time Clock ¦SM¦ 3.7 x 2.5 mm ¦ I2C Bus ¦ Ultra Low Power; Latest Revision Note: Created
footprint RTC-C3
pins: 1 VDD (power), 2 INT1 (out), 3 SCL, 4 SDA, 5 CLKOUT (out), 6 INT2 (out), 7 GND (power), 8 V_BACKUP, 9 NC, 10 NC2

## RV8564C3
designator U?  (value not drawn)
Real Time Clock ¦SM¦ 3.7 x 2.5 mm ¦ I2C Bus; Latest Revision Note: Created
footprint RTC-C3
pins: 1 CLKOE, 2 VDD (power), 3 CLKOUT (out), 4 SCL, 5 SDA, 6 INT (out), 7 GND (power), 8 NC, 9 NC2, 10 NC3

## RV8803C7
designator U?  (value not drawn)
Real Time Clock ¦SM¦ 3.2 x 1.5 mm ¦ I2C Bus ¦ Ultra Low Power. Temperature compensated; Latest Revision Note: Created
footprint RTC-C7
pins: 1 SDA, 2 CLKOUT (out), 3 VDD (power), 4 CLKOE, 5 GND (power), 6 INT (out), 7 EVI, 8 SCL

## SCOCXOHS
designator Y?  (value not drawn)
OCXO ¦14DIL¦ 20.1 x 12.52 mm ¦ 3.3V , 5.0V ¦ Frequency Range 10 - 120 MHz; Latest Revision Note: Created
footprint D0206-A
pins: 1 TUNE, 7 GND (power), 8 OP (out), 14 VDD (power)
